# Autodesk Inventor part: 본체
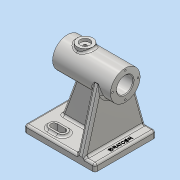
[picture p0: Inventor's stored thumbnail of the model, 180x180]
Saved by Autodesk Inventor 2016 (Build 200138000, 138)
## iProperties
Created: 2019-10
Part Number: 본체
Material: 알루미늄 6061
Document SubType Name: Modeling
Designer: Administrator
Density: 2.7 g/cm^3
Appearance: 알루미늄 - 평지
Mass: 591.136 g
Surface Area: 540.389 cm^2
Volume: 218.939 cm^3
Author: Administrator
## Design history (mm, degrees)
sketch "스케치1"
  geometry: L1 (-50, 43)-(50, 43); L2 (50, 43)-(50, -43); L3 (50, -43)-(-50, -43); L4 (-50, -43)-(-50, 43); L5 (-50, 43)-(50, -43); L6 (50, 43)-(-50, -43); 1 further point
  constraints: 12 end point, 2 midpoint, 2 parallel, 1 horizontal, 1 perpendicular
  dimensions: "d0" = 100 distance of L2.end L3.end; "d1" = 86 distance of L1.end L2.end
extrude "돌출1" new body sketch "스케치1" distance "d2" = 10; taper "d3" = 0 deg
sketch "스케치2"
  geometry: L1 (50.166, 86)-(-78.62, 86); L2 (-50, 0)-(50, 0) reference; L3 (-50, 0)-(-50, 10) reference; L4 (-50, 10)-(50, 10) reference; L5 (-50, 86)-(-50, 107); L6 (32, 86)-(32, 107); L7 (32, 107)-(-50, 107); L8 (-50, 97.5)-(-30, 97.5); L9 (-30, 97.5)-(-30, 100.5); L10 (-30, 100.5)-(32, 100.5); 1 further point
  constraints: 14 end point, 4 point on line, 3 perpendicular, 2 parallel, 1 horizontal, 1 vertical
  dimensions: "d5" = 86 distance between parallel lines of L1 L2; "d6" = 82 distance between parallel lines of L5 L6; "d7" = 42 diameter of L7 L1; "d8" = 23 diameter of L8 L1; "d9" = 29 diameter of L10 L1; "d10" = 62 distance between parallel lines of L9 L6
revolve "회전1" sketch "스케치2" stored, may be unused: angle "d11" = 90 deg
node "작업 평면2"
sketch "스케치4"
  geometry: L1 (0, 0)-(-10, 0) reference; L2 (0, 86)-(-10, 86) reference; L3 (0, 0)-(-10, 0) reference; L4 (-10, 0)-(-94.26, 23.693); L5 (0, 86)-(-10, 86) reference; L6 (-10, 86)-(-92.651, 62.919); L7 (-10, 0)-(-10, 86); L8 (0, 0)-(0, 86) reference; A1 r 21 centre (-86, 43) between (-94.26, 23.693) and (-92.651, 62.919) reference; 1 further point
  constraints: 6 end point, 2 point on circle, 1 parallel, 1 point on line
extrude "돌출2" join sketch "스케치4" distance "d16" = 10; taper "d17" = 0 deg
sketch "스케치5"
  geometry: L1 (50, 0)-(50, 10) reference; L2 (-25, 90.632)-(-25, 10) reference; L3 (35, 10)-(14.982, 65); L4 (-50, 65)-(32, 65) reference; L5 (-25, 10)-(50, 10) reference; 1 further point
  constraints: 2 end point, 1 point on line
  dimensions: "d18" = 15 distance from line of L3.start L1; "d79" = 70 deg angle of L5 L3; "d80" = 0 distance from line of L5 L3.start
feature "리브1" sketch "스케치5" dims "d20" = 1, "d21" = 10, "d22" = 0, "d23" = 0, "d24" = 1, "d25" = 1
node "작업 평면3"
sketch "스케치6"
  geometry: L1 (-32, 21)-(-32, -21) reference; C1 r 11 at (-7, 0); 1 further point
  constraints: 1 centre point
  dimensions: "d27" = 0 vertical distance of point (0, 0) C1.centre; "d28" = 25 distance from line of C1.centre L1; "d29" = 22 diameter of C1
extrude "돌출3" join sketch "스케치6" stored distance "d30" = 10; taper "d31" = 0 deg
sketch "스케치7"
  geometry: 2 further points
hole "구멍1" sketch "스케치7" at (0, 0) diameter "d32" = 4.917; stored, may be unused: countersink angle "d36" = 90 deg, drill point angle "d38" = 118 deg; dims "d33" = 12, "d34" = 4, "d35" = 2, "d37" = 17.1
sketch "스케치8"
  geometry: C1 r 2.458 at (0, 0) reference; C2 r 7 at (0, 0); 1 further point
  constraints: 1 centre point, 1 coincident
  dimensions: "d39" = 14 diameter of C2
extrude "돌출4" cut sketch "스케치8" distance "d40" = 4; taper "d41" = 0 deg
sketch "스케치9" dims "d42" = 36
  geometry: 3 further points
  constraints: 1 horizontal alignment, 2 other
hole "구멍2" sketch "스케치9" at (-18, 0) diameter "d43" = 2.459; stored, may be unused: countersink angle "d47" = 90 deg, drill point angle "d49" = 118 deg; dims "d44" = 8, "d45" = 4, "d46" = 2, "d48" = 10
node "작업 평면4"
sketch "스케치11"
  geometry: L1 (50, 43)-(50, -43) reference; 2 further points
  constraints: 1 horizontal alignment, 1 other
  dimensions: "d53" = 7 distance from line of point (43, 0) L1
feature "엠보싱1" sketch "스케치11" dims "d5" = 86, "d6" = 82, "d7" = 42, "d8" = 23, "d9" = 29, "d10" = 62, "d54" = 0.5, "d55" = 0
chamfer "모따기1" distance "d56" = 1; stored, may be unused: second distance "d57" = 2, angle "d58" = 45 deg
fillet "모깎기1" dims "d59" = 3
fillet "모깎기2" dims "d60" = 3
fillet "모깎기3" dims "d61" = 3
fillet "모깎기4" dims "d62" = 3
fillet "모깎기5" dims "d63" = 3
fillet "모깎기6" dims "d64" = 3
sketch "스케치12"
  geometry: L1 (-24, 22.5)-(-12, 22.5); L2 (-12, 22.5)-(-12, 31.5); L3 (-12, 31.5)-(-24, 31.5); L4 (-24, 31.5)-(-24, 22.5); L5 (-50, -43)-(-50, 43) reference; L6 (-24, 34)-(-12, 34); L7 (-12, 20)-(-24, 20); A1 r 4.5 centre (-12, 27) between (-12, 22.5) and (-12, 31.5); A2 r 4.5 centre (-24, 27) between (-24, 31.5) and (-24, 22.5); A3 r 7 centre (-12, 27) between (-12, 20) and (-12, 34); A4 r 7 centre (-24, 27) between (-24, 34) and (-24, 20); 1 further point
  constraints: 12 end point, 8 point on circle, 4 centre point, 3 parallel, 2 midpoint, 1 horizontal, 1 perpendicular, 3 other
  dimensions: "d66" = 12 distance of L1.start L1.end; "d67" = 26 distance between parallel lines of L4 L5; "d68" = 22.5 distance from line of L1 point (0, 0); "d69" = 9 distance of L3.end L1.start; "d70" = 2.5 distance between parallel lines of L3 L6
extrude "돌출5" join sketch "스케치12" distance "d71" = 3; taper "d72" = 0 deg
fillet "모깎기7" dims "d73" = 3
extrude "돌출6" cut sketch "스케치12" stored distance "d74" = 3; taper "d75" = 0 deg
sketch "스케치13"
  geometry: C1 r 11.5 at (0, 0) reference; 1 further point
extrude "돌출7" cut sketch "스케치13" stored distance "d76" = 3; taper "d77" = 0 deg
fillet "모깎기8" dims "d78" = 3
fillet "모깎기9" dims "d81" = 3
node "솔리드1"
pattern_circular "원형 패턴1" dims angle "d51" = 360 deg
mirror "대칭1"
mirror "대칭2"
other parameters: "d15" = -15
